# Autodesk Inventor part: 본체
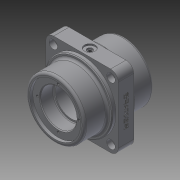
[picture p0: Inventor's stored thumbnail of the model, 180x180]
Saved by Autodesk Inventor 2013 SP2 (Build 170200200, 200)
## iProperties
Created: 2023-10
Part Number: 본체
Material: Generic
Document SubType Name: Modeling
Designer: i
Density: 1 g/cm^3
Author: i
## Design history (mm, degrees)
sketch "스케치1"
  geometry: L1 (-45, 0)-(45, 0); L2 (-45, 0)-(-45, 38); L3 (45, 38)-(45, 0); L4 (-45, 38)-(-15, 38); L5 (-15, 38)-(-15, 44); L6 (-15, 44)-(15, 44); L7 (15, 44)-(15, 38); L8 (15, 38)-(45, 38); 3 further points
  constraints: 16 end point, 4 horizontal, 4 vertical, 2 midpoint, 1 coincident, 1 vertical alignment
  dimensions: "d0" = 90 distance of L1.start L1.end; "d4" = 76 diameter of L4 L1; "d5" = 88 diameter of L6 L1; "d6" = 76 diameter of L8 L1; "d7" = 30 distance of L5.end L6.end
revolve "회전1" sketch "스케치1" stored, may be unused: angle "d3" = 90 deg
sketch "스케치2"
  geometry: L1 (-45, -38)-(-45, 38) reference; L2 (45, -38)-(45, 38) reference; L3 (-45, 0)-(45, 0); L4 (-45, 0)-(-45, 33); L5 (-41, 33)-(-41, 23.5); L6 (-41, 23.5)-(-24, 23.5); L7 (-24, 23.5)-(-24, 20.5); L8 (-24, 20.5)-(24, 20.5); L9 (24, 20.5)-(24, 23.5); L10 (24, 23.5)-(41, 23.5); L11 (41, 23.5)-(41, 33); L12 (41, 33)-(45, 33); L13 (-41, 33)-(-45, 33); 1 further point
  constraints: 22 end point, 5 horizontal, 4 vertical, 2 midpoint, 2 point on line
  dimensions: "d8" = 66 diameter of L13 L3; "d10" = 47 diameter of L6 L3; "d11" = 41 diameter of L8 L3; "d13" = 47 diameter of L10 L3; "d14" = 66 diameter of L12 L3; "d15" = 4 distance of L5.start L4.end; "d16" = 17 distance of L5.end L6.end; "d17" = 4 distance of L11.end L12.end; "d18" = 17 distance of L9.end L10.end
revolve "회전2" sketch "스케치2" stored, may be unused: angle "d19" = 90 deg
sketch "스케치3"
  geometry: L1 (-47, 47)-(47, 47); L2 (47, 47)-(47, -47); L3 (47, -47)-(-47, -47); L4 (-47, -47)-(-47, 47); L5 (-47, 47)-(47, -47); L6 (47, 47)-(-47, -47); C1 r 44 at (0, 0) reference; C2 r 44 at (0, 0); 1 further point
  constraints: 12 end point, 2 midpoint, 2 parallel, 1 centre point, 1 coincident, 1 concentric, 1 horizontal, 1 perpendicular
  dimensions: "d20" = 94 distance of L1.end L2.end; "d22" = 94 distance of L2.end L3.end
extrude "돌출1" join sketch "스케치3" stored distance "d23" = 20; taper "d24" = 0 deg
fillet "모깎기1" dims "d25" = 10
sketch "스케치4"
  geometry: 2 further points
  constraints: 1 coincident
hole "구멍1" sketch "스케치4" at (10, -37) diameter "d26" = 14; stored, may be unused: countersink angle "d30" = 90 deg, drill point angle "d32" = 0 deg; dims "d27" = 6, "d28" = 4, "d29" = 2, "d31" = 2
sketch "스케치9"
  geometry: L1 (0, 0)-(37.477, 37.477); L2 (0, 0)-(53, 0); C1 r 3.3 at (37.477, 37.477)
  constraints: 4 end point, 1 centre point, 1 coincident, 1 equal length, 1 horizontal
  dimensions: "d33" = 53 distance of L1.start L1.end; "d34" = 45 deg angle of L2 L1; "d35" = 6.6 diameter of C1
extrude "돌출2" cut sketch "스케치9" stored distance "d36" = 20; taper "d37" = 0 deg
sketch "스케치10"
  geometry: C1 r 3.3 at (-37.477, 37.477) reference; C2 r 3.3 at (-37.477, -37.477) reference; C3 r 3.3 at (37.477, -37.477) reference; C4 r 3.3 at (37.477, 37.477) reference; C5 r 5.5 at (-37.477, 37.477)
  constraints: 1 centre point, 1 coincident
  dimensions: "d41" = 11 diameter of C5
extrude "돌출3" cut sketch "스케치10" distance "d42" = 7; taper "d43" = 0 deg
sketch "스케치11"
  geometry: L1 (0, 0)-(0, 27); C1 r 33 at (0, 0) reference
  constraints: 2 end point, 1 vertical
  dimensions: "d47" = 27 distance of L1.start L1.end
hole "구멍2" sketch "스케치11" at (0, 27) diameter "d48" = 3.242; stored, may be unused: countersink angle "d52" = 90 deg, drill point angle "d54" = 118 deg; dims "d49" = 8, "d50" = 7, "d51" = 2, "d53" = 10
sketch "스케치12"
  geometry: L1 (0, 0)-(0, 27); C1 r 23.5 at (0, 0) reference
  constraints: 2 end point, 1 vertical
  dimensions: "d55" = 27 distance of L1.start L1.end
hole "구멍3" sketch "스케치12" at (0, 27) diameter "d56" = 3.242; stored, may be unused: countersink angle "d60" = 90 deg, drill point angle "d62" = 118 deg; dims "d57" = 8, "d58" = 7, "d59" = 2, "d61" = 10
sketch "스케치13"
  geometry: C1 r 7 at (0, 0) reference; C2 r 3.5 at (0, 0)
  constraints: 1 centre point, 1 coincident
  dimensions: "d66" = 7 diameter of C2
extrude "돌출4" cut sketch "스케치13" distance "d67" = 2; taper "d68" = 0 deg
hole "구멍4" diameter "d71" = 5.188; stored, may be unused: countersink angle "d75" = 90 deg, drill point angle "d77" = 118 deg; dims "d69" = 10, "d70" = 10, "d72" = 12, "d73" = 7, "d74" = 2, "d76" = 10
sketch "스케치14"
  geometry: L1 (0, 74)-(0, 84) reference; 2 further points
  constraints: 2 coincident, 1 other
  dimensions: "d78" = 10 distance from line of point (10, 37) L1 (derived)
feature "엠보싱1" sketch "스케치14" dims "d0" = 90, "d4" = 76, "d5" = 88, "d6" = 76, "d7" = 30, "d79" = 0.5, "d80" = 0
fillet "모깎기2" dims "d81" = 1
chamfer "모따기1" distance "d82" = 1; stored, may be unused: second distance "d83" = 2, angle "d84" = 45 deg
fillet "모깎기3" dims "d85" = 3
chamfer "모따기2" distance "d86" = 1; stored, may be unused: second distance "d87" = 2, angle "d88" = 45 deg
node "솔리드1"
pattern_circular "원형 패턴1" dims angle "d39" = 360 deg
mirror "대칭1"
pattern_circular "원형 패턴2" dims angle "d45" = 360 deg
pattern_circular "원형 패턴3" dims angle "d64" = 360 deg
